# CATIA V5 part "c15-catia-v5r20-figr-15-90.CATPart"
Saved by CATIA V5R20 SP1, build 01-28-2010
Part number: Part1
Bounding box of the stored display mesh (mm): x -51.577 to 65.644, y -33.321 to 33.748, z 0 to 1
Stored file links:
  D:\v5_r20\psrt_files_downloaded\c15\c15-catia-v5r20-figr-15-90.CATPart
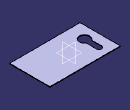
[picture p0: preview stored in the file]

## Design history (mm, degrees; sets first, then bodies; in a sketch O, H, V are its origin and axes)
SheetMetalParameters1: Thickness 1, BendRadius 5, KFactor 0.5 {= log(min(100,max(20*SheetMetalParameters1.BendRadius,SheetMetalParameters1.Thickness)/SheetMetalParameters1.Thickness))/log(100)/2}, ReliefRadialLength 1, ReliefAxialLength 2, MinimumBendRadius 0
Body1 (main body)
  Sketch1 on xy-plane, origin (0, 0, 0), H (1, 0, 0), V (0, 1, 0)
    line L1 (-51.5772, 33.7477) -> (65.6437, 33.7477)
    line L2 (65.6437, 33.7477) -> (65.6437, -33.3205)
    line L3 (65.6437, -33.3205) -> (-51.5772, -33.3205)
    line L4 (-51.5772, -33.3205) -> (-51.5772, 33.7477)
    horizontal: L1 H, L3 H
    vertical: L2 V, L4 V
  Wall1: Thickness 1, Profile Sketch1
  Sketch2 on face of Wall1, origin (0, 0, 1), H (1, 0, 0), V (0, 1, 0)
    construction line L1 (-31.7739, -5.9787) -> (-31.7739, 18.292)
    line L2 (-27.3923, 18.292) -> (-27.3923, 1.5188)
    line L3 (-36.1556, 1.5188) -> (-36.1556, 18.292)
    arc A1 centre (-31.7739, -5.9787) radius 8.6839 from (-27.3923, 1.5188) to (-36.1556, 1.5188) cw
    arc A2 centre (-31.7739, 18.292) radius 4.3816 from (-36.1556, 18.292) to (-27.3923, 18.292) cw
    radius A1 = 8.6839
    radius A2 = 4.3816
    vertical: L1 V
    tangency: A2 L2, A2 L3
    parallelism: L2 L3, L2 L1
  CutOut1: Direction Sketch2, EndLimit through (limit type 2), Orientation true, Profile Sketch2, StartLimit through (limit type 2)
